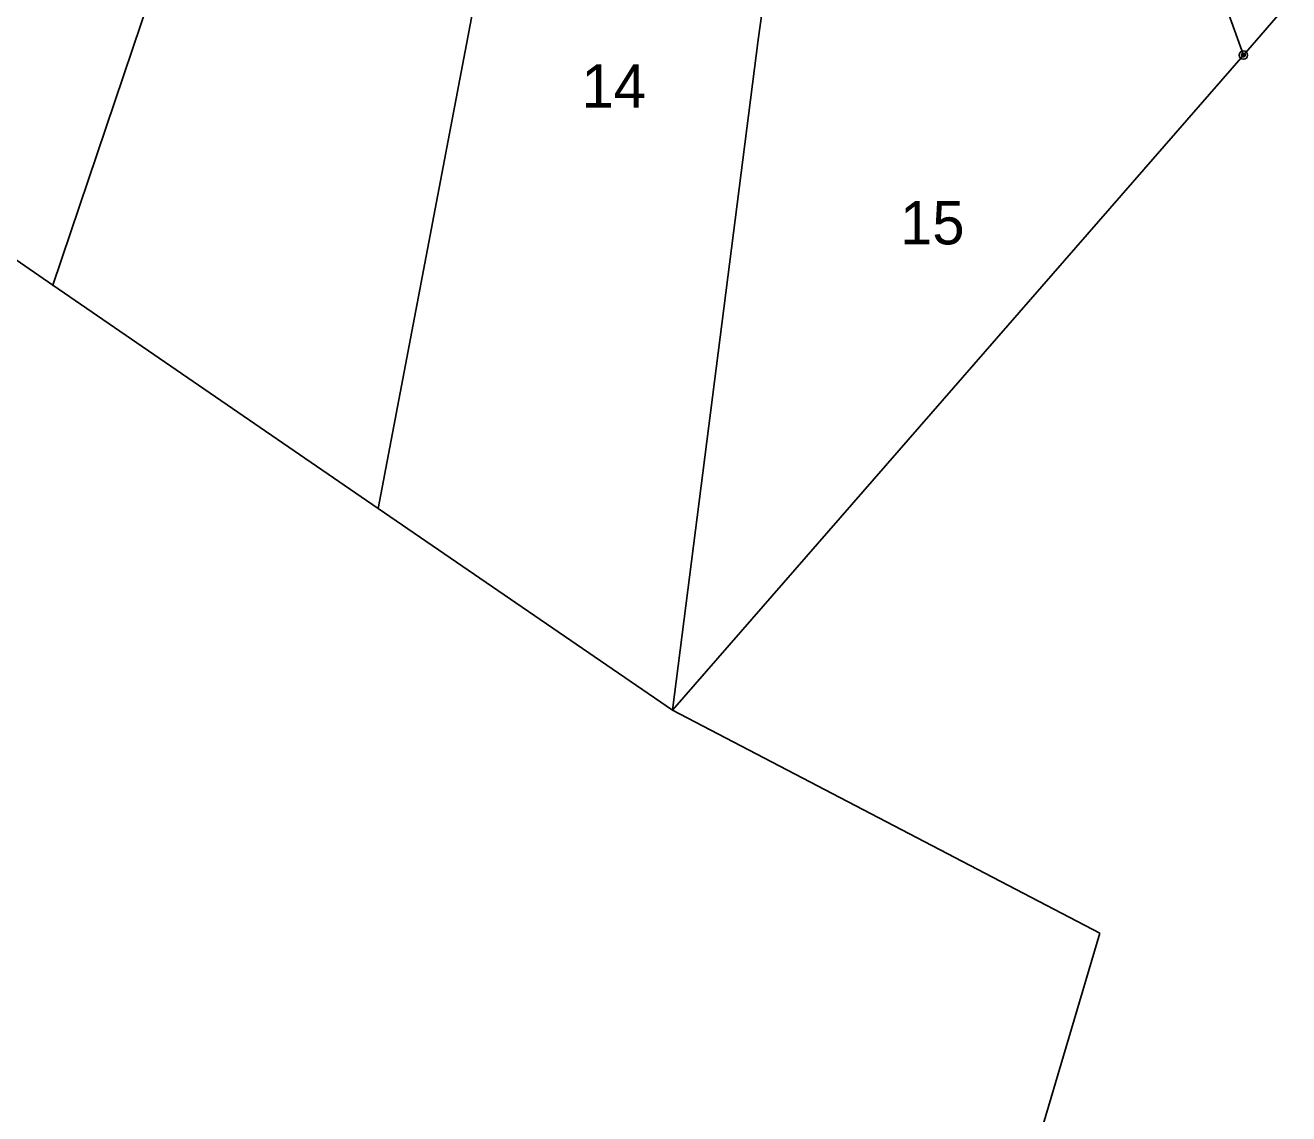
# Model space of a CAD drawing. Extents: x 1398271 to 1401121, y 1018936 to 1022764.
# Drawn here: x 1400405 to 1400930, y 1020889 to 1021342 of the extents above; entities that cross this region are included whole.
import ezdxf

# ---------------------------------------------------------------- set-up
doc = ezdxf.new("R2010")
doc.units = 0
for name, color, linetype in [('RD_EX_DV_Prop', 7, 'Continuous'), ('RD_EX_DV_PropPin', 7, 'Continuous'), ('RD_EX_DV_TX_Prop', 7, 'Continuous'), ('RD_EX_RW', 7, 'Continuous'), ('RD_SMD_Locator', 7, 'Continuous')]:
    doc.layers.add(name, color=color, linetype=linetype)

msp = doc.modelspace()

# ---------------------------------------------------------------- linework, layer by layer
at = {"layer": 'RD_EX_DV_Prop'}
for p, q in [((1400515.91, 1021528.77), (1400416.63, 1021233.98)), ((1400618.57, 1021492.71), (1400551.91, 1021141.1)), ((1400726.55, 1021455.03), (1400709.79, 1021336.01)), ((1400930.29, 1021351.3), (1400911.45, 1021329.65)), ((1400416.63, 1021233.98), (1400268.65, 1021335.59)), ((1400709.79, 1021336.01), (1400674.17, 1021057.16)), ((1400911.45, 1021329.65), (1400674.17, 1021057.16)), ((1400551.91, 1021141.1), (1400416.63, 1021233.98)), ((1400674.17, 1021057.16), (1400551.91, 1021141.1)), ((1400674.17, 1021057.16), (1400851.83, 1020964.47)), ((1400851.83, 1020964.47), (1400804.5, 1020804.99))]:
    msp.add_line(p, q, dxfattribs=at)
at = {"layer": 'RD_EX_DV_PropPin'}
for p, q in [((1400910.72, 1021329.45), (1400910.72, 1021329.84)), ((1400910.75, 1021329.35), (1400910.75, 1021329.95)), ((1400910.79, 1021329.28), (1400910.79, 1021330.02)), ((1400910.82, 1021329.22), (1400910.82, 1021330.07)), ((1400910.86, 1021329.17), (1400910.86, 1021330.12)), ((1400910.89, 1021329.13), (1400910.89, 1021330.16)), ((1400910.93, 1021329.1), (1400910.93, 1021330.2)), ((1400910.96, 1021329.07), (1400910.96, 1021330.23)), ((1400911, 1021329.04), (1400911, 1021330.26)), ((1400911.03, 1021329.01), (1400911.03, 1021330.28)), ((1400911.07, 1021328.99), (1400911.07, 1021330.3)), ((1400911.1, 1021328.97), (1400911.1, 1021330.32)), ((1400911.14, 1021328.96), (1400911.14, 1021330.34)), ((1400911.17, 1021328.94), (1400911.17, 1021330.36)), ((1400911.21, 1021328.93), (1400911.21, 1021330.37)), ((1400911.24, 1021328.92), (1400911.24, 1021330.38)), ((1400911.28, 1021328.91), (1400911.28, 1021330.39)), ((1400911.31, 1021328.9), (1400911.31, 1021330.4)), ((1400911.35, 1021328.89), (1400911.35, 1021330.4)), ((1400911.38, 1021328.89), (1400911.38, 1021330.41)), ((1400911.42, 1021328.89), (1400911.42, 1021330.41)), ((1400911.45, 1021328.89), (1400911.45, 1021330.41)), ((1400911.49, 1021328.89), (1400911.49, 1021330.41)), ((1400911.52, 1021328.89), (1400911.52, 1021330.41)), ((1400911.56, 1021328.89), (1400911.56, 1021330.4)), ((1400911.59, 1021328.9), (1400911.59, 1021330.4)), ((1400911.63, 1021328.91), (1400911.63, 1021330.39)), ((1400911.66, 1021328.92), (1400911.66, 1021330.38)), ((1400911.7, 1021328.93), (1400911.7, 1021330.37)), ((1400911.73, 1021328.94), (1400911.73, 1021330.36)), ((1400911.77, 1021328.96), (1400911.77, 1021330.34)), ((1400911.8, 1021328.97), (1400911.8, 1021330.32)), ((1400911.84, 1021328.99), (1400911.84, 1021330.3)), ((1400911.87, 1021329.01), (1400911.87, 1021330.28)), ((1400911.91, 1021329.04), (1400911.91, 1021330.26)), ((1400911.94, 1021329.07), (1400911.94, 1021330.23)), ((1400911.98, 1021329.1), (1400911.98, 1021330.2)), ((1400912.01, 1021329.13), (1400912.01, 1021330.16)), ((1400912.05, 1021329.17), (1400912.05, 1021330.12)), ((1400912.08, 1021329.22), (1400912.08, 1021330.07)), ((1400912.12, 1021329.28), (1400912.12, 1021330.02)), ((1400912.15, 1021329.35), (1400912.15, 1021329.95)), ((1400912.19, 1021329.45), (1400912.19, 1021329.84))]:
    msp.add_line(p, q, dxfattribs=at)
for radius in [1.75, 0.761]:
    msp.add_circle((1400911.45, 1021329.65), radius, dxfattribs=at)
at = {"layer": 'RD_EX_RW'}
msp.add_line((1400895.91, 1021373.19), (1400911.48, 1021329.67), dxfattribs=at)
at = {"layer": 'RD_SMD_Locator'}
msp.add_circle((1400911.45, 1021329.65), 0.15, dxfattribs=at)

# ---------------------------------------------------------------- texts
at = {"layer": 'RD_EX_DV_TX_Prop'}
for s, p in [('14', (1400636.36, 1021307.75)), ('15', (1400768.77, 1021250.91))]:
    msp.add_text(s, height=18, dxfattribs=at).set_placement(p)

doc.saveas('drawing.dxf')
